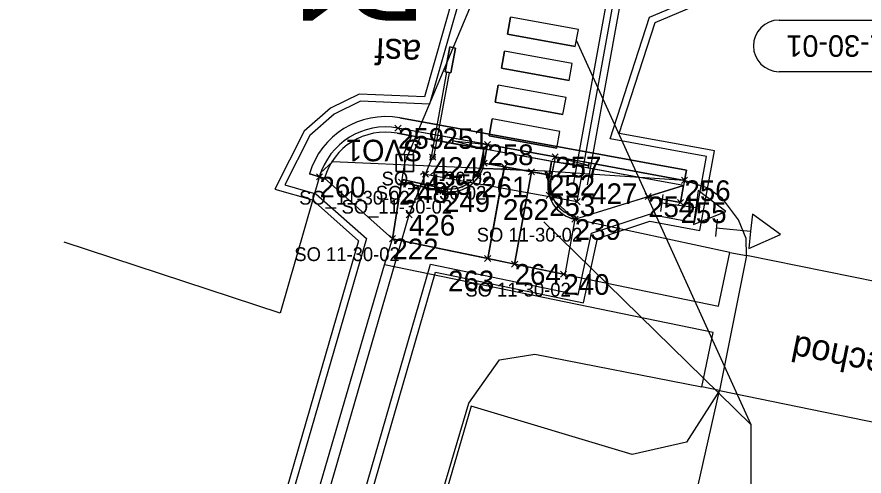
# Model space of a CAD drawing. Extents: x -728800 to -728100, y -1073200 to -1072700.
# Drawn here: x -728533.57 to -728508.97, y -1073070.14 to -1073056.81 of the extents above; entities that cross this region are included whole.
import ezdxf

# ---------------------------------------------------------------- set-up
doc = ezdxf.new("R2010")
doc.units = 0
for name, color, linetype in [('_NOR-návrh tenká obec', 7, 'Continuous'), ('_NOR-VDZ', 7, 'Continuous'), ('_NOR-šraf_+-0', 7, 'Continuous'), ('_NOR-šraf_+12', 7, 'Continuous'), ('_NOR-šraf_+6', 7, 'Continuous'), ('_NOR-šraf_bezbariéra', 7, 'Continuous'), ('_NOR-šraf_chodník', 7, 'Continuous'), ('_NOR-šraf_signální pás', 7, 'Continuous'), ('_NOR-šraf_varovný pás', 7, 'Continuous'), ('_NOR-šraf_vozovka', 7, 'Continuous'), ('_NOR-šraf_zeleň', 7, 'Continuous'), ('A2_OBVOD STAVBY', 7, 'Continuous'), ('B1_body_poloha', 7, 'Continuous'), ('B2_body_číslo', 7, 'Continuous'), ('B3_body_popiska', 7, 'Continuous'), ('B6_JŽM', 7, 'Continuous'), ('KOS_kabelová trasa VO', 7, 'Continuous'), ('KOS_nové prvky VO', 7, 'Continuous'), ('KTA_členění PS a SO', 7, 'Continuous'), ('ZA_02_Dočasný_do_1_roku', 7, 'Continuous')]:
    doc.layers.add(name, color=color, linetype=linetype)

msp = doc.modelspace()

# ---------------------------------------------------------------- linework, layer by layer
at = {"layer": '_NOR-návrh tenká obec'}
for p, q in [((-728519.325, -1073057.313), (-728519.235, -1073056.821)), ((-728517.267, -1073057.179), (-728519.235, -1073056.821)), ((-728517.357, -1073057.671), (-728519.325, -1073057.313)), ((-728517.357, -1073057.671), (-728517.267, -1073057.179)), ((-728519.504, -1073058.296), (-728519.414, -1073057.805)), ((-728517.447, -1073058.163), (-728519.414, -1073057.805)), ((-728517.536, -1073058.655), (-728519.504, -1073058.296)), ((-728517.536, -1073058.655), (-728517.447, -1073058.163)), ((-728519.683, -1073059.28), (-728519.593, -1073058.788)), ((-728517.626, -1073059.147), (-728519.593, -1073058.788)), ((-728517.716, -1073059.639), (-728519.683, -1073059.28)), ((-728517.716, -1073059.639), (-728517.626, -1073059.147)), ((-728519.862, -1073060.264), (-728519.773, -1073059.772)), ((-728517.805, -1073060.131), (-728519.773, -1073059.772)), ((-728517.895, -1073060.623), (-728519.862, -1073060.264)), ((-728517.895, -1073060.623), (-728517.805, -1073060.131)), ((-728520.013, -1073060.643), (-728520.904, -1073060.404)), ((-728520.904, -1073060.404), (-728519.907, -1073060.51)), ((-728518.045, -1073061.002), (-728518.124, -1073061.524)), ((-728517.967, -1073061.016), (-728518.077, -1073061.532)), ((-728517.967, -1073061.016), (-728516.969, -1073061.122)), ((-728516.969, -1073061.122), (-728517.94, -1073060.869)), ((-728519.416, -1073061.159), (-728519.9, -1073063.819)), ((-728518.629, -1073061.302), (-728519.117, -1073063.982)), ((-728522.668, -1073063.246), (-728524.642, -1073061.491)), ((-728520.176, -1073061.464), (-728520.242, -1073061.417)), ((-728514.211, -1073061.701), (-728514.301, -1073062.192)), ((-728518.116, -1073061.988), (-728518.039, -1073061.965)), ((-728517.366, -1073062.682), (-728515.241, -1073062.021)), ((-728517.366, -1073062.682), (-728517.657, -1073064.284)), ((-728517.29, -1073062.698), (-728517.29, -1073062.698))]:
    msp.add_line(p, q, dxfattribs=at)
for points in [[(-728514.184, -1073061.553), (-728514.13, -1073061.258), (-728522.452, -1073059.741)], [(-728514.184, -1073061.553), (-728522.506, -1073060.036)], [(-728514.184, -1073061.553), (-728514.211, -1073061.701), (-728522.533, -1073060.184)], [(-728520.918, -1073060.478), (-728520.891, -1073060.331)], [(-728519.907, -1073060.51), (-728520.008, -1073061.064)], [(-728520.087, -1073061.05), (-728520.013, -1073060.643)], [(-728518.117, -1073061.395), (-728520.006, -1073061.051)], [(-728518.045, -1073061.002), (-728518.141, -1073061.525)], [(-728517.94, -1073060.869), (-728518.062, -1073061.539)], [(-728516.956, -1073061.048), (-728516.983, -1073061.195)], [(-728525.075, -1073061.366), (-728524.786, -1073061.45)], [(-728524.642, -1073061.491), (-728524.786, -1073061.45)], [(-728521.201, -1073061.863), (-728522.401, -1073061.607), (-728522.388, -1073061.528), (-728521.184, -1073061.785)], [(-728514.301, -1073062.192), (-728515.241, -1073062.021)], [(-728517.349, -1073062.604), (-728517.366, -1073062.682)]]:
    msp.add_lwpolyline(points, dxfattribs=at)
for centre, radius, start, end in [((-728522.865, -1073062.004), 2.3, 79.6716, 163.9062), ((-728522.865, -1073062.004), 2, 79.6716, 163.9062), ((-728522.865, -1073062.004), 1.85, 79.6716, 163.9062), ((-728521.651, -1073060.659), 1.639, 331.5487, 0.5464), ((-728522.656, -1073060.141), 2.771, 332.0344, 349.2616), ((-728520.992, -1073060.885), 1, 257.9461, 349.6716), ((-728520.992, -1073060.885), 0.92, 257.9461, 349.6716), ((-728517.157, -1073061.704), 1, 169.6716, 257.9461), ((-728517.115, -1073061.648), 1.016, 172.9753, 198.8554), ((-728517.182, -1073061.755), 0.922, 166.0226, 193.9069), ((-728517.157, -1073061.704), 0.92, 169.6716, 257.9461)]:
    msp.add_arc(centre, radius, start, end, dxfattribs=at)
at = {"layer": '_NOR-VDZ'}
for p, q in [((-728519.325, -1073057.313), (-728519.235, -1073056.821)), ((-728517.267, -1073057.179), (-728519.235, -1073056.821)), ((-728517.357, -1073057.671), (-728519.325, -1073057.313)), ((-728517.357, -1073057.671), (-728517.267, -1073057.179)), ((-728519.504, -1073058.296), (-728519.414, -1073057.805)), ((-728517.447, -1073058.163), (-728519.414, -1073057.805)), ((-728517.536, -1073058.655), (-728519.504, -1073058.296)), ((-728517.536, -1073058.655), (-728517.447, -1073058.163)), ((-728519.683, -1073059.28), (-728519.593, -1073058.788)), ((-728517.626, -1073059.147), (-728519.593, -1073058.788)), ((-728517.716, -1073059.639), (-728519.683, -1073059.28)), ((-728517.716, -1073059.639), (-728517.626, -1073059.147)), ((-728519.862, -1073060.264), (-728519.773, -1073059.772)), ((-728517.805, -1073060.131), (-728519.773, -1073059.772)), ((-728517.895, -1073060.623), (-728519.862, -1073060.264)), ((-728517.895, -1073060.623), (-728517.805, -1073060.131))]:
    msp.add_line(p, q, dxfattribs=at)
for points in [[(-728517.357, -1073057.671), (-728517.267, -1073057.179), (-728519.235, -1073056.821), (-728519.325, -1073057.313), (-728517.357, -1073057.671)], [(-728517.536, -1073058.655), (-728517.447, -1073058.163), (-728519.414, -1073057.805), (-728519.504, -1073058.296), (-728517.536, -1073058.655)], [(-728517.716, -1073059.639), (-728517.626, -1073059.147), (-728519.593, -1073058.788), (-728519.683, -1073059.28), (-728517.716, -1073059.639)], [(-728517.895, -1073060.623), (-728517.805, -1073060.131), (-728519.773, -1073059.772), (-728519.862, -1073060.264), (-728517.895, -1073060.623)]]:
    msp.add_lwpolyline(points, dxfattribs=at)
at = {"layer": '_NOR-šraf_+-0'}
for points in [[(-728518.039, -1073061.965), (-728518.077, -1073061.977), (-728518.116, -1073061.988)], [(-728517.366, -1073062.682), (-728517.349, -1073062.604)]]:
    msp.add_lwpolyline(points, dxfattribs=at)
for radius in [1, 0.92]:
    msp.add_arc((-728517.157, -1073061.704), radius, 196.5034, 257.9461, dxfattribs=at)
at = {"layer": '_NOR-šraf_+12'}
msp.add_line((-728524.786, -1073061.45), (-728524.642, -1073061.491), dxfattribs=at)
for points in [[(-728522.533, -1073060.184), (-728521.989, -1073060.283), (-728521.929, -1073060.141), (-728522.506, -1073060.036)], [(-728520.918, -1073060.478), (-728520.904, -1073060.404), (-728520.891, -1073060.331), (-728521.929, -1073060.141), (-728521.989, -1073060.283), (-728520.918, -1073060.478)], [(-728516.983, -1073061.195), (-728516.969, -1073061.122), (-728516.956, -1073061.048), (-728514.184, -1073061.553), (-728514.211, -1073061.701), (-728516.983, -1073061.195)]]:
    msp.add_lwpolyline(points, dxfattribs=at)
for radius in [2, 1.85]:
    msp.add_arc((-728522.865, -1073062.004), radius, 79.6716, 163.9062, dxfattribs=at)
at = {"layer": '_NOR-šraf_+6'}
for points in [[(-728521.184, -1073061.785), (-728522.388, -1073061.528), (-728522.401, -1073061.607)], [(-728520.176, -1073061.464), (-728520.209, -1073061.441), (-728520.211, -1073061.439), (-728520.242, -1073061.417)], [(-728522.401, -1073061.607), (-728521.201, -1073061.863)]]:
    msp.add_lwpolyline(points, dxfattribs=at)
for radius in [1, 0.92]:
    msp.add_arc((-728520.992, -1073060.885), radius, 257.9461, 324.641, dxfattribs=at)
at = {"layer": '_NOR-šraf_bezbariéra'}
msp.add_lwpolyline([(-728519.934, -1073060.658), (-728519.907, -1073060.51), (-728517.94, -1073060.869), (-728517.967, -1073061.016), (-728519.934, -1073060.658)], dxfattribs=at)
at = {"layer": '_NOR-šraf_chodník'}
for p, q in [((-728518.145, -1073061.548), (-728518.197, -1073061.381)), ((-728518.197, -1073061.381), (-728518.145, -1073061.548))]:
    msp.add_line(p, q, dxfattribs=at)
for points in [[(-728520.008, -1073061.064), (-728520.006, -1073061.051), (-728519.416, -1073061.159), (-728519.429, -1073061.233), (-728520.045, -1073061.206)], [(-728520.045, -1073061.206), (-728519.429, -1073061.233), (-728519.9, -1073063.819), (-728522.668, -1073063.246)], [(-728519.117, -1073063.982), (-728518.629, -1073061.302), (-728518.197, -1073061.381)], [(-728518.197, -1073061.381), (-728518.117, -1073061.395), (-728518.141, -1073061.525)], [(-728522.668, -1073063.246), (-728522.401, -1073061.607), (-728521.201, -1073061.863)], [(-728517.37, -1073062.681), (-728517.366, -1073062.682), (-728517.657, -1073064.284), (-728519.117, -1073063.982)]]:
    msp.add_lwpolyline(points, dxfattribs=at)
for centre, start, end in [((-728520.992, -1073060.885), 341.2678, 349.6716), ((-728520.992, -1073060.885), 324.641, 341.2678), ((-728520.992, -1073060.885), 257.9461, 324.641), ((-728517.157, -1073061.704), 171.0403, 196.5034), ((-728517.157, -1073061.704), 169.6716, 171.0403), ((-728517.157, -1073061.704), 196.5034, 257.6848)]:
    msp.add_arc(centre, 1, start, end, dxfattribs=at)
at = {"layer": '_NOR-šraf_signální pás'}
for points in [[(-728519.429, -1073061.233), (-728518.877, -1073061.257), (-728518.629, -1073061.302), (-728519.117, -1073063.982), (-728519.9, -1073063.819), (-728519.429, -1073061.233)], [(-728519.416, -1073061.159), (-728518.877, -1073061.257), (-728519.429, -1073061.233), (-728519.416, -1073061.159)]]:
    msp.add_lwpolyline(points, dxfattribs=at)
at = {"layer": '_NOR-šraf_varovný pás'}
msp.add_lwpolyline([(-728520.006, -1073061.051), (-728519.416, -1073061.159), (-728518.629, -1073061.302), (-728518.117, -1073061.395), (-728518.045, -1073061.002), (-728519.934, -1073060.658), (-728520.006, -1073061.051), (-728520.006, -1073061.051)], dxfattribs=at)
at = {"layer": '_NOR-šraf_vozovka'}
for points in [[(-728522.452, -1073059.741), (-728514.13, -1073061.258), (-728514.184, -1073061.553), (-728516.956, -1073061.048), (-728517.94, -1073060.869), (-728519.907, -1073060.51), (-728522.506, -1073060.036)], [(-728524.786, -1073061.45), (-728525.075, -1073061.366), (-728525.075, -1073061.366)]]:
    msp.add_lwpolyline(points, dxfattribs=at)
for radius in [2.3, 2]:
    msp.add_arc((-728522.865, -1073062.004), radius, 79.6716, 163.9062, dxfattribs=at)
at = {"layer": '_NOR-šraf_zeleň'}
for points in [[(-728522.533, -1073060.184), (-728522.115, -1073060.26), (-728522.341, -1073060.799), (-728522.56, -1073060.799), (-728522.56, -1073061.299), (-728522.31, -1073061.299), (-728522.06, -1073061.299), (-728522.06, -1073060.799), (-728522.07, -1073060.799), (-728521.863, -1073060.306), (-728520.013, -1073060.643), (-728520.087, -1073061.05)], [(-728517.349, -1073062.604), (-728517.366, -1073062.682), (-728514.211, -1073061.701), (-728517.967, -1073061.016), (-728518.062, -1073061.539)], [(-728521.184, -1073061.785), (-728522.388, -1073061.528), (-728522.401, -1073061.607), (-728522.668, -1073063.246), (-728524.642, -1073061.491)], [(-728514.832, -1073062.096), (-728514.301, -1073062.192), (-728514.211, -1073061.701), (-728515.241, -1073062.021), (-728514.832, -1073062.096), (-728514.832, -1073062.096)]]:
    msp.add_lwpolyline(points, dxfattribs=at)
for centre, radius, start, end in [((-728522.865, -1073062.004), 1.85, 79.6716, 163.9062), ((-728520.992, -1073060.885), 0.92, 324.641, 349.6716), ((-728520.992, -1073060.885), 0.92, 257.9461, 324.641), ((-728517.157, -1073061.704), 0.92, 169.6716, 196.5034), ((-728517.157, -1073061.704), 0.92, 196.5034, 257.9461)]:
    msp.add_arc(centre, radius, start, end, dxfattribs=at)
at = {"layer": 'A2_OBVOD STAVBY'}
for points in [[(-728520.331, -1073054.186), (-728521.735, -1073059.131), (-728523.635, -1073059.049), (-728524.468, -1073059.462), (-728525.229, -1073060.125), (-728526.082, -1073061.804), (-728524.989, -1073062.12), (-728523.652, -1073063.308), (-728524.386, -1073065.843), (-728528.221, -1073079.089)], [(-728526.571, -1073082.019), (-728521.417, -1073064.22), (-728517.12, -1073065.11), (-728516.715, -1073063.238), (-728515.187, -1073062.742), (-728514.306, -1073062.903), (-728513.737, -1073063.007), (-728513.316, -1073060.695), (-728513.62, -1073060.639), (-728516.085, -1073060.19), (-728515.041, -1073056.967), (-728511.798, -1073055.597)]]:
    msp.add_lwpolyline(points, dxfattribs=at)
at = {"layer": 'B1_body_poloha'}
for p, q in [((-728522.595, -1073059.948), (-728522.418, -1073060.125)), ((-728522.595, -1073060.125), (-728522.418, -1073059.948)), ((-728519.995, -1073060.422), (-728519.819, -1073060.598)), ((-728519.995, -1073060.598), (-728519.819, -1073060.422)), ((-728521.588, -1073060.792), (-728521.411, -1073060.969)), ((-728521.588, -1073060.969), (-728521.411, -1073060.792)), ((-728518.028, -1073060.78), (-728517.851, -1073060.957)), ((-728518.028, -1073060.957), (-728517.851, -1073060.78)), ((-728520.094, -1073060.963), (-728519.918, -1073061.139)), ((-728520.094, -1073061.139), (-728519.918, -1073060.963)), ((-728521.798, -1073061.286), (-728521.621, -1073061.463)), ((-728521.798, -1073061.463), (-728521.621, -1073061.286)), ((-728519.504, -1073061.071), (-728519.328, -1073061.247)), ((-728519.504, -1073061.247), (-728519.328, -1073061.071)), ((-728518.717, -1073061.214), (-728518.541, -1073061.39)), ((-728518.717, -1073061.39), (-728518.541, -1073061.214)), ((-728518.205, -1073061.307), (-728518.029, -1073061.483)), ((-728518.205, -1073061.483), (-728518.029, -1073061.307)), ((-728524.874, -1073061.362), (-728524.698, -1073061.538)), ((-728524.874, -1073061.538), (-728524.698, -1073061.362)), ((-728522.489, -1073061.518), (-728522.312, -1073061.695)), ((-728522.489, -1073061.695), (-728522.312, -1073061.518)), ((-728520.264, -1073061.376), (-728520.088, -1073061.552)), ((-728520.264, -1073061.552), (-728520.088, -1073061.376)), ((-728514.272, -1073061.465), (-728514.096, -1073061.641)), ((-728514.272, -1073061.641), (-728514.096, -1073061.465)), ((-728521.289, -1073061.775), (-728521.112, -1073061.951)), ((-728521.289, -1073061.951), (-728521.112, -1073061.775)), ((-728518.204, -1073061.9), (-728518.028, -1073062.076)), ((-728518.204, -1073062.076), (-728518.028, -1073061.9)), ((-728515.329, -1073061.933), (-728515.153, -1073062.109)), ((-728515.329, -1073062.109), (-728515.153, -1073061.933)), ((-728517.395, -1073062.083), (-728517.218, -1073062.26)), ((-728517.395, -1073062.26), (-728517.218, -1073062.083)), ((-728514.389, -1073062.104), (-728514.213, -1073062.28)), ((-728514.389, -1073062.28), (-728514.213, -1073062.104)), ((-728522.273, -1073062.467), (-728522.096, -1073062.644)), ((-728522.273, -1073062.644), (-728522.096, -1073062.467)), ((-728517.454, -1073062.594), (-728517.277, -1073062.77)), ((-728517.454, -1073062.77), (-728517.277, -1073062.594)), ((-728522.756, -1073063.158), (-728522.58, -1073063.334)), ((-728522.756, -1073063.334), (-728522.58, -1073063.158)), ((-728519.989, -1073063.731), (-728519.812, -1073063.908)), ((-728519.989, -1073063.908), (-728519.812, -1073063.731)), ((-728519.205, -1073063.894), (-728519.029, -1073064.07)), ((-728519.205, -1073064.07), (-728519.029, -1073063.894)), ((-728517.789, -1073064.187), (-728517.613, -1073064.363)), ((-728517.789, -1073064.363), (-728517.613, -1073064.187))]:
    msp.add_line(p, q, dxfattribs=at)
at = {"layer": 'B2_body_číslo'}
for p, q in [((-728521.003, -1073057.682), (-728521.003, -1073057.682)), ((-728520.836, -1073057.712), (-728520.836, -1073057.712)), ((-728521.135, -1073058.406), (-728521.135, -1073058.406)), ((-728520.968, -1073058.436), (-728520.968, -1073058.436)), ((-728522.506, -1073060.036), (-728522.506, -1073060.036)), ((-728519.907, -1073060.51), (-728519.907, -1073060.51)), ((-728520.006, -1073061.051), (-728520.006, -1073061.051)), ((-728517.94, -1073060.869), (-728517.94, -1073060.869)), ((-728519.416, -1073061.159), (-728519.416, -1073061.159)), ((-728518.629, -1073061.302), (-728518.629, -1073061.302)), ((-728524.786, -1073061.45), (-728524.786, -1073061.45)), ((-728520.176, -1073061.464), (-728520.176, -1073061.464)), ((-728518.117, -1073061.395), (-728518.117, -1073061.395)), ((-728514.184, -1073061.553), (-728514.184, -1073061.553)), ((-728522.401, -1073061.607), (-728522.401, -1073061.607)), ((-728521.17, -1073061.869), (-728521.17, -1073061.869)), ((-728518.116, -1073061.988), (-728518.116, -1073061.988)), ((-728515.241, -1073062.021), (-728515.241, -1073062.021)), ((-728514.301, -1073062.192), (-728514.301, -1073062.192)), ((-728517.37, -1073062.681), (-728517.37, -1073062.681)), ((-728522.668, -1073063.246), (-728522.668, -1073063.246)), ((-728519.9, -1073063.819), (-728519.9, -1073063.819)), ((-728519.117, -1073063.982), (-728519.117, -1073063.982)), ((-728517.701, -1073064.275), (-728517.701, -1073064.275))]:
    msp.add_line(p, q, dxfattribs=at)
at = {"layer": 'B6_JŽM'}
for p, q in [((-728522.31, -1073061.049), (-728518.67, -1073052.375)), ((-728522.668, -1073063.246), (-728522.31, -1073061.049)), ((-728514.814, -1073061.961), (-728514.88, -1073062.457)), ((-728513.234, -1073062.681), (-728513.286, -1073063.179))]:
    msp.add_line(p, q, dxfattribs=at)
for points in [[(-728522.31, -1073061.299), (-728522.56, -1073061.299), (-728522.56, -1073060.799), (-728522.06, -1073060.799), (-728522.06, -1073061.299), (-728522.31, -1073061.299), (-728522.31, -1073060.799)], [(-728512.38, -1073063.734), (-728512.393, -1073063.245), (-728512.614, -1073062.698), (-728513.079, -1073062.079), (-728513.527, -1073061.773), (-728514.184, -1073061.553), (-728518.227, -1073061.285), (-728524.406, -1073061.017), (-728524.753, -1073061.334), (-728525.929, -1073065.41), (-728532.201, -1073063.347)], [(-728512.865, -1073063.643), (-728517.37, -1073062.681), (-728517.956, -1073062.15), (-728518.227, -1073061.285)], [(-728514.847, -1073062.209), (-728513.856, -1073062.341), (-728513.922, -1073062.836), (-728512.988, -1073062.456), (-728513.79, -1073061.845), (-728513.856, -1073062.341)], [(-728513.26, -1073062.93), (-728512.265, -1073063.032), (-728512.316, -1073063.53), (-728511.395, -1073063.122), (-728512.214, -1073062.535), (-728512.265, -1073063.032)], [(-728513.171, -1073067.654), (-728513.679, -1073067.545), (-728513.348, -1073065.972), (-728522.9, -1073064.007), (-728522.668, -1073063.246), (-728513.2, -1073065.207), (-728512.865, -1073063.643), (-728512.38, -1073063.734)], [(-728505.498, -1073065.132), (-728512.38, -1073063.734), (-728513.171, -1073067.654), (-728506.273, -1073069.065), (-728505.498, -1073065.132)], [(-728533.573, -1073083.015), (-728532.804, -1073079.821), (-728527.933, -1073081.215), (-728522.9, -1073064.007)], [(-728531.131, -1073104.759), (-728528.363, -1073095.064), (-728524.847, -1073082.829), (-728520.445, -1073068.019), (-728519.555, -1073066.763), (-728518.532, -1073066.599), (-728513.679, -1073067.545)], [(-728513.171, -1073067.654), (-728514.129, -1073069.149), (-728515.701, -1073069.511), (-728520.385, -1073068.108), (-728525.367, -1073085.199), (-728528.271, -1073095.025), (-728524.268, -1073096.199), (-728523.716, -1073096.605), (-728523.622, -1073097.442)], [(-728524.69, -1073104.648), (-728518.127, -1073087.402), (-728515.708, -1073078.91), (-728513.171, -1073067.654)]]:
    msp.add_lwpolyline(points, dxfattribs=at)
at = {"layer": 'KOS_kabelová trasa VO'}
for p, q in [((-728515.932, -1073053.526), (-728517.409, -1073061.613)), ((-728515.538, -1073053.598), (-728517.015, -1073061.684))]:
    msp.add_line(p, q, dxfattribs=at)
for points in [[(-728528.739, -1073080.192), (-728527.396, -1073080.554), (-728522.184, -1073062.556), (-728521.71, -1073061.375), (-728517.306, -1073062.171), (-728515.639, -1073053.015), (-728515.016, -1073053.113), (-728515.09, -1073053.601)], [(-728521.71, -1073061.375), (-728521.499, -1073060.881)]]:
    msp.add_lwpolyline(points, dxfattribs=at)
at = {"layer": 'KOS_nové prvky VO'}
for p, q in [((-728521.527, -1073060.82), (-728521.089, -1073058.414)), ((-728521.452, -1073060.834), (-728521.014, -1073058.428))]:
    msp.add_line(p, q, dxfattribs=at)
msp.add_lwpolyline([(-728521.135, -1073058.406), (-728521.003, -1073057.682), (-728520.836, -1073057.712), (-728520.968, -1073058.436)], close=True, dxfattribs=at)
msp.add_lwpolyline([(-728520.968, -1073058.436), (-728520.836, -1073057.712), (-728521.003, -1073057.682), (-728521.135, -1073058.406), (-728520.968, -1073058.436)], dxfattribs=at)
msp.add_circle((-728521.499, -1073060.881), 0.0665, dxfattribs=at)
at = {"layer": 'KTA_členění PS a SO'}
for p, q in [((-728512.245, -1073068.65), (-728517.324, -1073057.492)), ((-728512.245, -1073068.65), (-728518.265, -1073062.753)), ((-728512.245, -1073071.034), (-728512.245, -1073068.65))]:
    msp.add_line(p, q, dxfattribs=at)
for points in [[(-728511.438, -1073056.9), (-728506.438, -1073056.9)], [(-728506.438, -1073058.4), (-728511.438, -1073058.4)]]:
    msp.add_lwpolyline(points, dxfattribs=at)
msp.add_arc((-728511.432, -1073057.65), 0.75, 90.4529, 269.5471, dxfattribs=at)
at = {"layer": 'ZA_02_Dočasný_do_1_roku'}
msp.add_lwpolyline([(-728520.113, -1073054.153), (-728521.586, -1073059.338), (-728523.592, -1073059.251), (-728524.356, -1073059.629), (-728525.069, -1073060.25), (-728525.794, -1073061.679), (-728524.89, -1073061.94), (-728523.424, -1073063.243), (-728526.138, -1073072.616), (-728528.083, -1073079.333), (-728529.444, -1073078.966), (-728529.965, -1073080.897), (-728526.708, -1073081.775), (-728524.133, -1073072.881), (-728521.558, -1073063.987), (-728517.274, -1073064.874), (-728516.886, -1073063.083), (-728515.201, -1073062.537), (-728513.898, -1073062.774), (-728513.549, -1073060.856), (-728516.346, -1073060.346), (-728515.203, -1073056.818), (-728511.189, -1073055.123)], dxfattribs=at)

# ---------------------------------------------------------------- texts
at = {"layer": 'B2_body_číslo'}
for s, p in [('259', (-728522.506, -1073060.636)), ('251', (-728521.21, -1073060.639)), ('258', (-728519.907, -1073061.11)), ('424', (-728521.499, -1073061.481)), ('257', (-728517.94, -1073061.469)), ('260', (-728524.786, -1073062.05)), ('425', (-728521.71, -1073061.975)), ('261', (-728520.086, -1073062.047)), ('252', (-728518.117, -1073061.995)), ('256', (-728514.184, -1073062.153)), ('248', (-728522.401, -1073062.207)), ('427', (-728516.893, -1073062.241)), ('249', (-728521.17, -1073062.469)), ('253', (-728518.116, -1073062.588)), ('254', (-728515.241, -1073062.621)), ('262', (-728519.456, -1073062.7)), ('255', (-728514.301, -1073062.792)), ('426', (-728522.184, -1073063.156)), ('239', (-728517.37, -1073063.281)), ('222', (-728522.668, -1073063.846)), ('264', (-728519.117, -1073064.582)), ('263', (-728521.052, -1073064.774)), ('240', (-728517.701, -1073064.875))]:
    msp.add_text(s, height=0.6, dxfattribs=at).set_placement(p)
at = {"layer": 'B3_body_popiska'}
for s, p in [('SO_11-30-02', (-728522.982, -1073061.701)), ('SO_11-30-02', (-728523.152, -1073062.114)), ('SO_11-30-02', (-728525.377, -1073062.257)), ('SO_11-30-02', (-728524.146, -1073062.519)), ('SO 11-30-02', (-728520.219, -1073063.331)), ('SO 11-30-02', (-728525.517, -1073063.896)), ('SO 11-30-02', (-728520.55, -1073064.925))]:
    msp.add_text(s, height=0.4, dxfattribs=at).set_placement(p)
at = {"layer": 'B6_JŽM'}
for s, rotation, p in [('asf', 177.5165, (-728521.818, -1073057.484)), ('přechod', 168.5173, (-728507.432, -1073066.758))]:
    msp.add_text(s, height=0.75, rotation=rotation, dxfattribs=at).set_placement(p)
at = {"layer": 'KOS_nové prvky VO'}
msp.add_text('SVO1', height=0.625, rotation=180, dxfattribs=at).set_placement((-728521.785, -1073060.374))
at = {"layer": 'KTA_členění PS a SO'}
msp.add_text('SO 11-30-01', height=0.625, rotation=180, dxfattribs=at).set_placement((-728506.439, -1073057.341))
at = {"layer": 'ZA_02_Dočasný_do_1_roku'}
msp.add_text('D1', height=2.5, rotation=180, dxfattribs=at).set_placement((-728521.71, -1073054.418))

doc.saveas('drawing.dxf')
